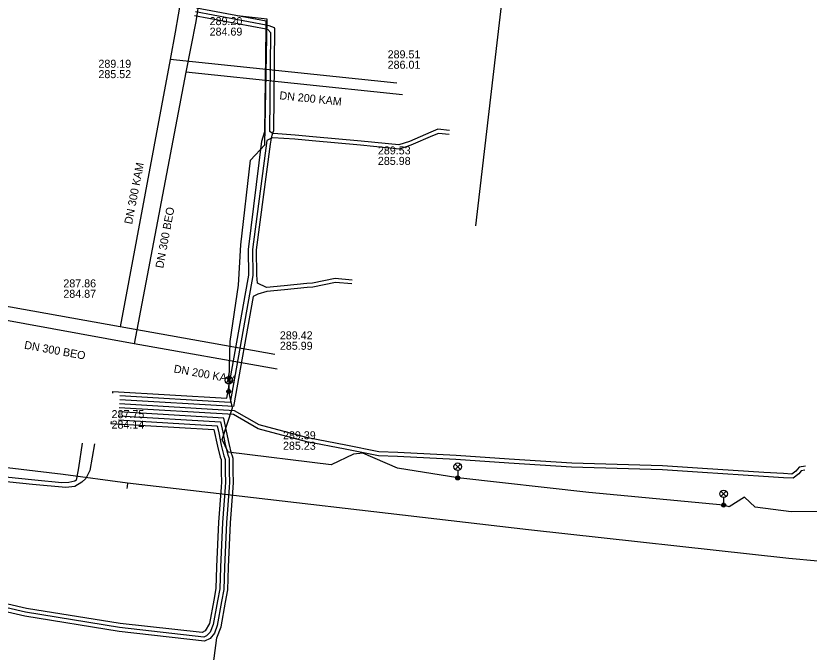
# Model space of a CAD drawing. Extents: x -595540 to -593988, y -1160850 to -1159202.
# Drawn here: x -594500 to -594420.8, y -1160421.9 to -1160358.3 of the extents above; entities that cross this region are included whole.
import ezdxf

# ---------------------------------------------------------------- set-up
doc = ezdxf.new("R2010")
doc.units = 0
for name, color, linetype in [('BVK-DESTOVA_popisy', 7, 'Continuous'), ('BVK-DESTOVA_trasa sítě', 7, 'Continuous'), ('BVK-SPLASKOVA_popisy', 7, 'Continuous'), ('BVK-SPLASKOVA_trasa sítě', 7, 'Continuous'), ('BVK-VODOVOD_trasa sítě', 7, 'Continuous'), ('CETIN_kabel podzemní', 7, 'Continuous'), ('EON-NN_kabel', 7, 'Continuous'), ('EON-VN_kabel', 7, 'Continuous'), ('TSB_kabel VO', 7, 'Continuous'), ('TSB_lampy VO', 7, 'Continuous')]:
    doc.layers.add(name, color=color, linetype=linetype)

msp = doc.modelspace()

# ---------------------------------------------------------------- linework, layer by layer
at = {"layer": 'BVK-DESTOVA_popisy'}
for p, q in [((-594480.682, -1160359.391), (-594480.682, -1160359.391)), ((-594463.865, -1160372.31), (-594463.865, -1160372.31)), ((-594490.482, -1160398.665), (-594490.482, -1160398.665)), ((-594473.35, -1160400.775), (-594473.35, -1160400.775))]:
    msp.add_line(p, q, dxfattribs=at)
at = {"layer": 'BVK-DESTOVA_trasa sítě'}
for p, q in [((-594480.547, -1160348.932), (-594482.06, -1160358.898)), ((-594461.399, -1160366.23), (-594483.046, -1160363.977)), ((-594488.218, -1160391.1), (-594508.377, -1160387.435)), ((-594473.92, -1160393.654), (-594488.218, -1160391.1))]:
    msp.add_line(p, q, dxfattribs=at)
msp.add_lwpolyline([(-594482.06, -1160358.898), (-594483.046, -1160363.977), (-594488.218, -1160391.1)], dxfattribs=at)
at = {"layer": 'BVK-SPLASKOVA_popisy'}
for p, q in [((-594462.891, -1160361.785), (-594462.891, -1160361.785)), ((-594491.795, -1160362.726), (-594491.795, -1160362.726)), ((-594495.301, -1160384.674), (-594495.301, -1160384.674)), ((-594473.661, -1160389.866), (-594473.661, -1160389.866))]:
    msp.add_line(p, q, dxfattribs=at)
at = {"layer": 'BVK-SPLASKOVA_trasa sítě'}
for p, q in [((-594482.034, -1160347.812), (-594484.109, -1160359.973)), ((-594461.97, -1160365.068), (-594484.609, -1160362.717)), ((-594489.609, -1160389.418), (-594510.032, -1160385.734)), ((-594474.18, -1160392.167), (-594489.609, -1160389.418))]:
    msp.add_line(p, q, dxfattribs=at)
msp.add_lwpolyline([(-594484.109, -1160359.973), (-594484.609, -1160362.717), (-594489.609, -1160389.418)], dxfattribs=at)
at = {"layer": 'BVK-VODOVOD_trasa sítě'}
for points in [[(-594414.938, -1160415.755), (-594416.18, -1160415.71), (-594419.89, -1160412.84), (-594422.8, -1160412.56), (-594448.8, -1160409.7), (-594488.88, -1160405.03), (-594495.32, -1160404.17), (-594508.771, -1160402.588)], [(-594488.88, -1160405.03), (-594488.92, -1160405.353), (-594488.961, -1160405.578)]]:
    msp.add_lwpolyline(points, dxfattribs=at)
at = {"layer": 'CETIN_kabel podzemní'}
msp.add_lwpolyline([(-594451.047, -1160353.001), (-594454.119, -1160379.331)], dxfattribs=at)
at = {"layer": 'EON-NN_kabel'}
for points in [[(-594490.364, -1160396.051), (-594490.354, -1160395.867), (-594478.963, -1160396.546), (-594477.047, -1160385.906), (-594476.815, -1160384.618), (-594476.751, -1160384.262), (-594476.786, -1160381.679), (-594475.454, -1160370.846), (-594475.156, -1160369.882), (-594475.036, -1160359.678), (-594475.031, -1160359.272), (-594475.026, -1160358.867), (-594482.007, -1160357.561)], [(-594456.71, -1160369.795), (-594457.881, -1160369.676), (-594458.575, -1160369.974), (-594460.706, -1160370.889), (-594461.765, -1160371.242), (-594465.549, -1160370.854), (-594470.383, -1160370.424), (-594472.142, -1160370.271), (-594474.29, -1160370.089), (-594474.36, -1160370.066), (-594474.481, -1160370.025), (-594474.67, -1160369.895), (-594474.569, -1160360.033), (-594474.859, -1160359.706), (-594475.002, -1160359.684), (-594475.036, -1160359.678), (-594482.187, -1160358.341)], [(-594466.426, -1160384.736), (-594468.132, -1160384.575), (-594470.411, -1160385.05), (-594470.972, -1160385.1), (-594473.238, -1160385.317), (-594474.994, -1160385.482), (-594475.91, -1160385.056), (-594475.952, -1160384.262), (-594475.986, -1160381.725), (-594474.607, -1160371.174), (-594474.483, -1160370.575), (-594474.417, -1160370.254), (-594474.36, -1160370.066), (-594474.328, -1160369.961), (-594474.269, -1160369.786), (-594474.165, -1160359.639), (-594474.214, -1160359.536), (-594474.725, -1160359.322), (-594474.935, -1160359.29), (-594475.031, -1160359.272), (-594482.097, -1160357.951)], [(-594456.757, -1160370.192), (-594457.819, -1160370.084), (-594458.417, -1160370.342), (-594460.564, -1160371.263), (-594461.721, -1160371.648), (-594465.587, -1160371.252), (-594470.419, -1160370.822), (-594472.174, -1160370.669), (-594474.362, -1160370.518), (-594474.483, -1160370.575), (-594474.961, -1160370.798), (-594476.386, -1160381.702), (-594476.351, -1160384.295), (-594478.632, -1160396.967), (-594489.646, -1160396.312)], [(-594466.466, -1160385.134), (-594468.11, -1160384.979), (-594470.353, -1160385.446), (-594470.936, -1160385.498), (-594473.2, -1160385.715), (-594474.956, -1160385.88), (-594475.865, -1160386.159), (-594476.32, -1160386.376), (-594478.301, -1160397.387), (-594489.67, -1160396.711)], [(-594421.142, -1160403.332), (-594421.764, -1160403.439), (-594422.08, -1160403.825), (-594422.486, -1160404.127), (-594423.317, -1160404.087), (-594425.309, -1160403.973), (-594431.407, -1160403.565), (-594435.414, -1160403.299), (-594438.806, -1160403.21), (-594444.496, -1160403.045), (-594450.743, -1160402.627), (-594456.046, -1160402.284), (-594461.881, -1160401.98), (-594463.758, -1160401.892), (-594467.054, -1160401.248), (-594470.874, -1160400.513), (-594475.714, -1160399.222), (-594478.204, -1160397.793), (-594489.694, -1160397.109)], [(-594480.573, -1160425.046), (-594479.949, -1160420.497), (-594479.54, -1160419.378), (-594479.099, -1160416.941), (-594478.849, -1160415.697), (-594478.784, -1160413.444), (-594478.606, -1160409.002), (-594478.328, -1160405.498), (-594478.302, -1160404.945), (-594478.302, -1160404.684), (-594478.314, -1160404.133), (-594478.327, -1160403.437), (-594478.341, -1160402.57), (-594478.388, -1160402.34), (-594478.493, -1160402.077), (-594478.735, -1160401.075), (-594478.986, -1160399.852), (-594479.273, -1160398.531), (-594489.741, -1160397.908)], [(-594421.191, -1160403.746), (-594421.549, -1160403.808), (-594421.802, -1160404.116), (-594422.362, -1160404.534), (-594423.339, -1160404.487), (-594425.333, -1160404.373), (-594431.433, -1160403.965), (-594435.432, -1160403.699), (-594438.818, -1160403.61), (-594444.516, -1160403.445), (-594450.769, -1160403.027), (-594456.07, -1160402.684), (-594461.901, -1160402.38), (-594463.806, -1160402.29), (-594467.13, -1160401.64), (-594470.964, -1160400.903), (-594475.816, -1160399.608), (-594478.295, -1160398.189), (-594489.718, -1160397.509)], [(-594489.765, -1160398.307), (-594479.599, -1160398.912), (-594479.377, -1160399.935), (-594479.125, -1160401.162), (-594478.875, -1160402.198), (-594478.773, -1160402.455), (-594478.74, -1160402.614), (-594478.727, -1160403.444), (-594478.714, -1160404.141), (-594478.702, -1160404.688), (-594478.702, -1160404.936), (-594478.727, -1160405.473), (-594479.005, -1160408.978), (-594479.184, -1160413.43), (-594479.248, -1160415.652), (-594479.492, -1160416.866), (-594479.926, -1160419.267), (-594480.205, -1160420.038), (-594480.642, -1160420.55), (-594481.182, -1160420.823), (-594489.736, -1160419.842), (-594499.148, -1160418.33), (-594507.543, -1160416.392)], [(-594489.789, -1160398.706), (-594479.926, -1160399.293), (-594479.769, -1160400.017), (-594479.515, -1160401.25), (-594479.257, -1160402.32), (-594479.157, -1160402.569), (-594479.14, -1160402.658), (-594479.127, -1160403.45), (-594479.114, -1160404.149), (-594479.102, -1160404.692), (-594479.102, -1160404.926), (-594479.127, -1160405.447), (-594479.405, -1160408.954), (-594479.584, -1160413.416), (-594479.646, -1160415.606), (-594479.884, -1160416.79), (-594480.312, -1160419.155), (-594480.611, -1160419.917), (-594480.999, -1160420.283), (-594481.255, -1160420.412), (-594489.681, -1160419.446), (-594499.071, -1160417.937), (-594507.441, -1160416.005)], [(-594490.53, -1160398.881), (-594490.54, -1160399.062), (-594480.247, -1160399.676), (-594479.905, -1160401.337), (-594479.639, -1160402.442), (-594479.543, -1160402.682), (-594479.539, -1160402.699), (-594479.527, -1160403.457), (-594479.514, -1160404.157), (-594479.502, -1160404.696), (-594479.502, -1160404.916), (-594479.526, -1160405.422), (-594479.804, -1160408.93), (-594479.984, -1160413.402), (-594480.045, -1160415.561), (-594480.277, -1160416.715), (-594480.698, -1160419.044), (-594481.125, -1160419.792), (-594481.41, -1160419.96), (-594489.626, -1160419.05), (-594498.994, -1160417.544), (-594507.339, -1160415.618)]]:
    msp.add_lwpolyline(points, dxfattribs=at)
at = {"layer": 'EON-VN_kabel'}
for points in [[(-594493.408, -1160401.037), (-594493.774, -1160403.505), (-594493.944, -1160404.397), (-594494.023, -1160404.739), (-594494.148, -1160404.82), (-594494.767, -1160404.983), (-594495.443, -1160404.99), (-594498.143, -1160404.744), (-594504.051, -1160404.136), (-594510.328, -1160403.578), (-594512.254, -1160402.746), (-594512.85, -1160402.223), (-594513.095, -1160401.769), (-594513.368, -1160401.285), (-594513.229, -1160398.643), (-594512.315, -1160389.542), (-594511.399, -1160378.471), (-594510.528, -1160368.834), (-594510.142, -1160365.02), (-594508.851, -1160358.091), (-594507.908, -1160352.983)], [(-594492.175, -1160401.095), (-594492.656, -1160403.76), (-594493.05, -1160404.563), (-594493.462, -1160404.951), (-594494.164, -1160405.357), (-594495.038, -1160405.477), (-594498.379, -1160405.186), (-594504.24, -1160404.567), (-594510.529, -1160404.007), (-594510.99, -1160403.74)]]:
    msp.add_lwpolyline(points, dxfattribs=at)
at = {"layer": 'TSB_kabel VO'}
msp.add_lwpolyline([(-594419.319, -1160407.857), (-594422.571, -1160407.888), (-594426.145, -1160407.429), (-594427.219, -1160406.449), (-594428.745, -1160407.398), (-594429.316, -1160407.228), (-594442.794, -1160405.959), (-594455.885, -1160404.517), (-594461.919, -1160403.527), (-594465.361, -1160402.051), (-594466.296, -1160402.149), (-594468.525, -1160403.214), (-594478.831, -1160401.931), (-594479.412, -1160400.682), (-594478.383, -1160397.512), (-594478.763, -1160395.874), (-594478.618, -1160390.874), (-594477.808, -1160385.241), (-594477.559, -1160381.206), (-594476.61, -1160372.777), (-594475.15, -1160371.232), (-594474.943, -1160358.678), (-594477.944, -1160358.337)], dxfattribs=at)
at = {"layer": 'TSB_lampy VO'}
for p, q in [((-594479.028, -1160395.014), (-594478.498, -1160394.484)), ((-594479.028, -1160394.484), (-594478.498, -1160395.014)), ((-594479.028, -1160395.014), (-594478.498, -1160394.484)), ((-594479.028, -1160394.484), (-594478.498, -1160395.014)), ((-594478.763, -1160395.124), (-594478.763, -1160395.874)), ((-594478.763, -1160395.124), (-594478.763, -1160395.874)), ((-594456.15, -1160403.657), (-594455.62, -1160403.127)), ((-594456.15, -1160403.127), (-594455.62, -1160403.657)), ((-594456.15, -1160403.657), (-594455.62, -1160403.127)), ((-594456.15, -1160403.127), (-594455.62, -1160403.657)), ((-594455.885, -1160403.767), (-594455.885, -1160404.517)), ((-594455.885, -1160403.767), (-594455.885, -1160404.517)), ((-594429.581, -1160406.368), (-594429.051, -1160405.838)), ((-594429.581, -1160405.838), (-594429.051, -1160406.368)), ((-594429.581, -1160406.368), (-594429.051, -1160405.838)), ((-594429.581, -1160405.838), (-594429.051, -1160406.368)), ((-594429.316, -1160406.478), (-594429.316, -1160407.228)), ((-594429.316, -1160406.478), (-594429.316, -1160407.228))]:
    msp.add_line(p, q, dxfattribs=at)
for centre, radius in [((-594478.763, -1160394.749), 0.375), ((-594478.763, -1160394.749), 0.375), ((-594478.763, -1160395.874), 0.2), ((-594478.763, -1160395.874), 0.2), ((-594478.763, -1160395.874), 0.145), ((-594478.763, -1160395.874), 0.145), ((-594478.763, -1160395.874), 0.0876), ((-594478.763, -1160395.874), 0.0876), ((-594455.885, -1160403.392), 0.375), ((-594455.885, -1160403.392), 0.375), ((-594455.885, -1160404.517), 0.2), ((-594455.885, -1160404.517), 0.2), ((-594455.885, -1160404.517), 0.145), ((-594455.885, -1160404.517), 0.145), ((-594455.885, -1160404.517), 0.0876), ((-594455.885, -1160404.517), 0.0876), ((-594429.316, -1160406.103), 0.375), ((-594429.316, -1160406.103), 0.375), ((-594429.316, -1160407.228), 0.2), ((-594429.316, -1160407.228), 0.2), ((-594429.316, -1160407.228), 0.145), ((-594429.316, -1160407.228), 0.145), ((-594429.316, -1160407.228), 0.0876), ((-594429.316, -1160407.228), 0.0876)]:
    msp.add_circle(centre, radius, dxfattribs=at)

# ---------------------------------------------------------------- texts
at = {"layer": 'BVK-DESTOVA_popisy'}
for s, p in [('289.20', (-594480.682, -1160359.266)), ('284.69', (-594480.682, -1160360.316)), ('289.53', (-594463.865, -1160372.185)), ('285.98', (-594463.865, -1160373.235)), ('287.75', (-594490.482, -1160398.54)), ('284.14', (-594490.482, -1160399.59)), ('289.39', (-594473.35, -1160400.65)), ('285.23', (-594473.35, -1160401.7))]:
    msp.add_text(s, height=0.8, dxfattribs=at).set_placement(p)
for s, rotation, p in [('DN 200 KAM', 354.05683, (-594473.732, -1160366.669)), ('DN 300 BEO', 79.41232, (-594485.325, -1160383.61)), ('DN 300 BEO', 349.72167, (-594499.254, -1160391.591)), ('DN 200 KAM', 349.87229, (-594484.311, -1160393.972))]:
    msp.add_text(s, height=0.8, rotation=rotation, dxfattribs=at).set_placement(p)
at = {"layer": 'BVK-SPLASKOVA_popisy'}
for s, p in [('289.51', (-594462.891, -1160362.585)), ('289.19', (-594491.795, -1160363.526)), ('286.01', (-594462.891, -1160363.625)), ('285.52', (-594491.795, -1160364.566)), ('287.86', (-594495.301, -1160385.474)), ('284.87', (-594495.301, -1160386.514)), ('289.42', (-594473.661, -1160390.666)), ('285.99', (-594473.661, -1160391.706))]:
    msp.add_text(s, height=0.8, dxfattribs=at).set_placement(p)
msp.add_text('DN 300 KAM', height=0.8, rotation=78.91645, dxfattribs=at).set_placement((-594488.437, -1160379.213))

doc.saveas('drawing.dxf')
